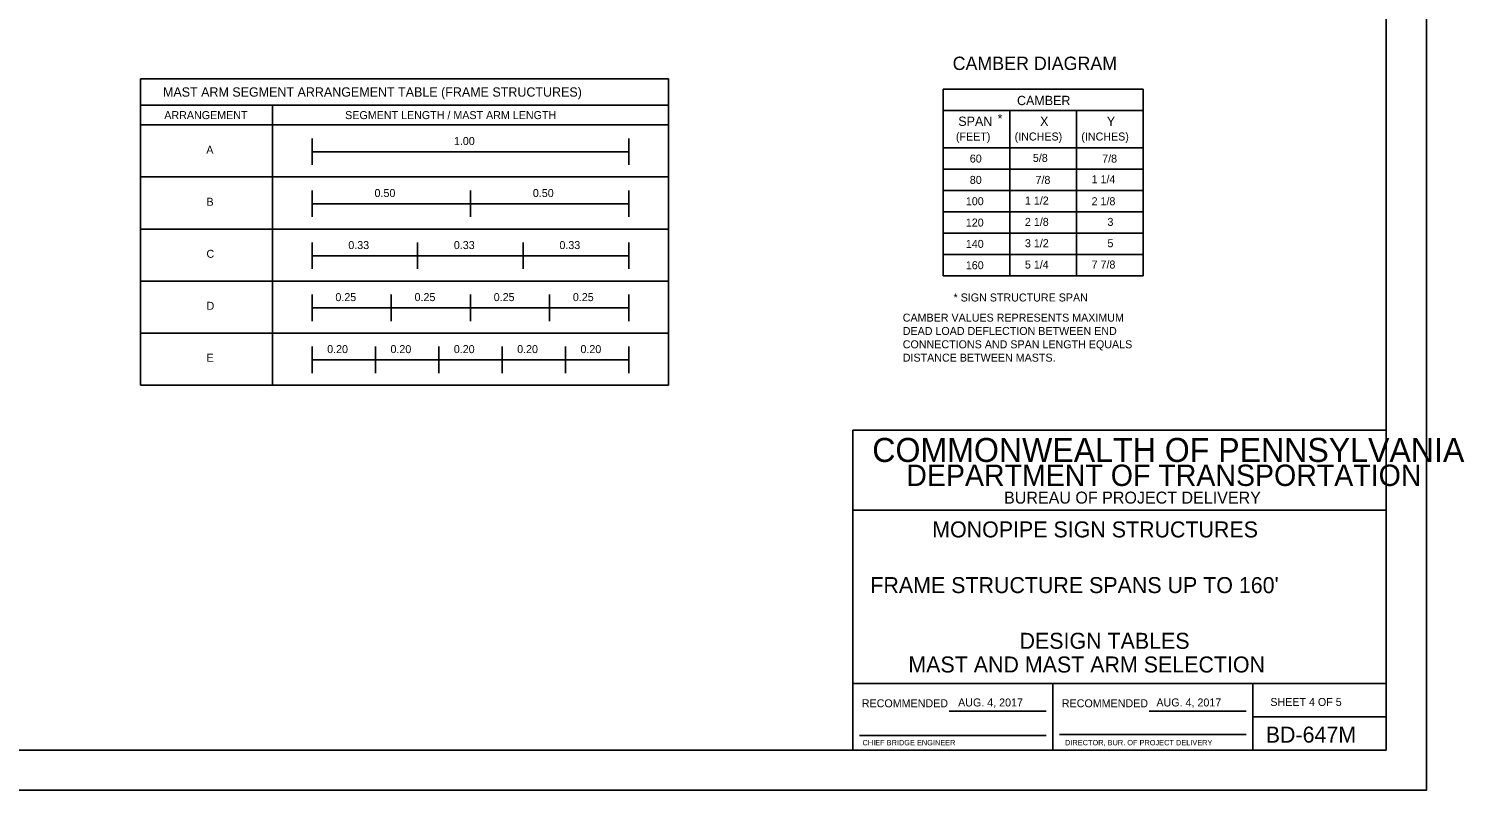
# Model space of a CAD drawing. Extents: x 640117 to 642655, y 297247 to 298435.
# Drawn here: x 641275 to 641814, y 297247 to 297533 of the extents above; entities that cross this region are included whole.
import ezdxf

# ---------------------------------------------------------------- set-up
doc = ezdxf.new("R2010")
doc.units = 0
for name, color, linetype in [('1', 7, 'Continuous'), ('10', 7, 'Continuous'), ('2', 7, 'Continuous'), ('3', 7, 'Continuous'), ('52', 7, 'Continuous'), ('53', 7, 'Continuous'), ('PLT-BNDY', 7, 'Continuous')]:
    doc.layers.add(name, color=color, linetype=linetype)

msp = doc.modelspace()

# ---------------------------------------------------------------- linework, layer by layer
at = {"layer": '1'}
for p, q in [((641659.46, 297262.46), (641659.46, 297287.46)), ((641620.54, 297277.17), (641656.96, 297277.17)), ((641695.54, 297277.17), (641731.96, 297277.17)), ((641586.96, 297267.96), (641656.96, 297267.96)), ((641661.96, 297268.33), (641731.96, 297268.33))]:
    msp.add_line(p, q, dxfattribs=at)
at = {"layer": '2'}
for p, q in [((641784.46, 297826.46), (641784.46, 297262.46)), ((641784.46, 297382.46), (641584.46, 297382.46)), ((641584.46, 297382.46), (641584.46, 297262.46)), ((641784.46, 297262.46), (641784.46, 297382.46)), ((641784.46, 297352.46), (641584.46, 297352.46)), ((641784.46, 297287.46), (641584.46, 297287.46)), ((641734.46, 297287.46), (641734.46, 297262.46)), ((641734.46, 297274.96), (641784.46, 297274.96)), ((641784.46, 297262.46), (640998.46, 297262.46)), ((641584.46, 297262.46), (641784.46, 297262.46))]:
    msp.add_line(p, q, dxfattribs=at)
at = {"layer": '3'}
for p, q in [((641317.35, 297514.26), (641515.24, 297514.26)), ((641317.35, 297514.26), (641317.35, 297399.41)), ((641515.24, 297514.26), (641515.24, 297399.41)), ((641618.23, 297510.34), (641693.23, 297510.34)), ((641618.23, 297510.34), (641618.23, 297440.35)), ((641693.23, 297510.34), (641693.23, 297440.35)), ((641317.35, 297504.36), (641515.24, 297504.36)), ((641366.83, 297504.36), (641366.83, 297399.41)), ((641618.23, 297502.34), (641693.23, 297502.34)), ((641643.23, 297502.34), (641643.23, 297440.35)), ((641668.23, 297502.34), (641668.23, 297440.35)), ((641317.35, 297496.94), (641515.24, 297496.94)), ((641381.67, 297491.85), (641381.67, 297481.95)), ((641500.4, 297491.85), (641500.4, 297481.95)), ((641381.67, 297486.9), (641500.4, 297486.9)), ((641618.23, 297488.34), (641693.23, 297488.34)), ((641618.23, 297480.34), (641693.23, 297480.34)), ((641317.35, 297477.44), (641515.24, 297477.44)), ((641381.67, 297472.34), (641381.67, 297462.45)), ((641441.03, 297472.34), (641441.03, 297462.45)), ((641500.4, 297472.34), (641500.4, 297462.45)), ((641618.23, 297472.35), (641693.23, 297472.35)), ((641381.67, 297467.39), (641441.03, 297467.39)), ((641441.03, 297467.39), (641500.4, 297467.39)), ((641618.23, 297464.35), (641693.23, 297464.35)), ((641317.35, 297457.93), (641515.24, 297457.93)), ((641381.67, 297452.83), (641381.67, 297442.94)), ((641421.24, 297452.83), (641421.24, 297442.94)), ((641460.82, 297452.83), (641460.82, 297442.94)), ((641500.4, 297452.83), (641500.4, 297442.94)), ((641618.23, 297456.35), (641693.23, 297456.35)), ((641381.67, 297447.89), (641421.24, 297447.89)), ((641421.24, 297447.89), (641460.82, 297447.89)), ((641460.82, 297447.89), (641500.4, 297447.89)), ((641618.23, 297448.35), (641693.23, 297448.35)), ((641317.35, 297438.42), (641515.24, 297438.42)), ((641618.23, 297440.35), (641693.23, 297440.35)), ((641381.67, 297433.33), (641381.67, 297423.43)), ((641411.35, 297433.33), (641411.35, 297423.43)), ((641441.03, 297433.33), (641441.03, 297423.43)), ((641470.71, 297433.33), (641470.71, 297423.43)), ((641500.4, 297433.33), (641500.4, 297423.43)), ((641381.67, 297428.38), (641411.35, 297428.38)), ((641411.35, 297428.38), (641441.03, 297428.38)), ((641441.03, 297428.38), (641470.71, 297428.38)), ((641470.71, 297428.38), (641500.4, 297428.38)), ((641317.35, 297418.91), (641515.24, 297418.91)), ((641381.67, 297413.82), (641381.67, 297403.93)), ((641405.41, 297413.82), (641405.41, 297403.93)), ((641429.16, 297413.82), (641429.16, 297403.93)), ((641452.9, 297413.82), (641452.9, 297403.93)), ((641476.65, 297413.82), (641476.65, 297403.93)), ((641500.4, 297413.82), (641500.4, 297403.93)), ((641381.67, 297408.87), (641405.41, 297408.87)), ((641405.41, 297408.87), (641429.16, 297408.87)), ((641429.16, 297408.87), (641452.9, 297408.87)), ((641452.9, 297408.87), (641476.65, 297408.87)), ((641476.65, 297408.87), (641500.4, 297408.87)), ((641317.35, 297399.41), (641515.24, 297399.41))]:
    msp.add_line(p, q, dxfattribs=at)
at = {"layer": 'PLT-BNDY'}
msp.add_lwpolyline([(640958.46, 297841.46), (641799.46, 297841.46), (641799.46, 297247.46), (640958.46, 297247.46)], close=True, dxfattribs=at)

# ---------------------------------------------------------------- texts
at = {"layer": '1'}
for s, height, p in [('RECOMMENDED', 3, (641587.79, 297278.58)), ('RECOMMENDED', 3, (641662.79, 297278.58)), ('CHIEF BRIDGE ENGINEER', 2.0002, (641588.05, 297264.33)), ('DIRECTOR, BUR. OF PROJECT DELIVERY', 2.0002, (641664, 297264.33))]:
    msp.add_text(s, height=height, dxfattribs=at).set_placement(p)
at = {"layer": '10'}
for s, p in [('MONOPIPE SIGN STRUCTURES', (641614.18, 297342.28)), ("FRAME STRUCTURE SPANS UP TO 160'", (641590.98, 297321.4)), ('DESIGN TABLES', (641646.92, 297300.51)), ('MAST AND MAST ARM SELECTION', (641605.23, 297291.63)), ('BD-647M', (641739.25, 297265.33))]:
    msp.add_text(s, height=6, dxfattribs=at).set_placement(p)
at = {"layer": '2'}
for s, height, p in [('COMMONWEALTH OF PENNSYLVANIA', 9, (641591.71, 297370.58)), ('DEPARTMENT OF TRANSPORTATION', 8.0002, (641604.46, 297361.58)), ('BUREAU OF PROJECT DELIVERY', 4.5, (641641.12, 297354.96)), ('SHEET 4 OF 5', 3, (641740.97, 297279.08))]:
    msp.add_text(s, height=height, dxfattribs=at).set_placement(p)
at = {"layer": '52'}
for p in [(641623.89, 297278.89), (641698.25, 297278.89)]:
    msp.add_text('AUG. 4, 2017', height=3, dxfattribs=at).set_placement(p)
at = {"layer": '53'}
for s, height, p in [('CAMBER DIAGRAM', 5, (641621.84, 297517.57)), ('MAST ARM SEGMENT ARRANGEMENT TABLE (FRAME STRUCTURES)', 3.5, (641325.75, 297507.56)), ('CAMBER', 3.5, (641645.98, 297504.38)), ('ARRANGEMENT', 3, (641326.23, 297499.15)), ('SEGMENT LENGTH / MAST ARM LENGTH', 3, (641394.06, 297499.15)), ('*', 3.5, (641638.7, 297497.61)), ('SPAN', 3.5, (641623.96, 297496.59)), ('X', 3.5, (641654.64, 297496.59)), ('Y', 3.5, (641679.64, 297496.59)), ('1.00', 3, (641434.83, 297489.42)), ('(FEET)', 3, (641623.07, 297491.12)), ('(INCHES)', 3, (641645.09, 297491.12)), ('(INCHES)', 3, (641670.09, 297491.12)), ('A', 3, (641341.98, 297486.16)), ('60', 3, (641628.28, 297482.84)), ('5/8 ', 3, (641651.92, 297483.1)), ('7/8', 3, (641677.91, 297482.84)), ('80', 3, (641628.28, 297474.85)), ('7/8', 3, (641652.91, 297474.85)), ('1 1/4', 3, (641673.94, 297475.1)), ('B', 3, (641342.04, 297466.65)), ('0.50', 3, (641405.07, 297469.92)), ('0.50', 3, (641464.44, 297469.92)), ('100', 3, (641626.79, 297466.85)), ('1 1/2', 3, (641648.94, 297467.1)), ('2 1/8', 3, (641673.94, 297466.85)), ('120', 3, (641626.79, 297458.85)), ('2 1/8', 3, (641648.94, 297459.1)), ('3', 3, (641679.89, 297459.1)), ('0.33', 3, (641395.24, 297450.41)), ('0.33', 3, (641434.81, 297450.41)), ('0.33', 3, (641474.39, 297450.41)), ('140', 3, (641626.79, 297450.85)), ('3 1/2', 3, (641648.94, 297451.11)), ('5', 3, (641679.89, 297451.11)), ('C', 3, (641342.05, 297447.14)), ('160', 3, (641626.79, 297442.85)), ('5 1/4', 3, (641648.94, 297443.11)), ('7 7/8', 3, (641673.94, 297443.11)), ('D', 3, (641342.08, 297427.63)), ('0.25', 3, (641390.39, 297430.9)), ('0.25', 3, (641420.08, 297430.9)), ('0.25', 3, (641449.76, 297430.9)), ('0.25', 3, (641479.44, 297430.9)), ('* SIGN STRUCTURE SPAN', 3, (641622.17, 297430.76)), ('CAMBER VALUES REPRESENTS MAXIMUM', 3, (641603.13, 297423.2)), ('DEAD LOAD DEFLECTION BETWEEN END', 3, (641603.13, 297418.2)), ('0.20', 3, (641387.3, 297411.4)), ('0.20', 3, (641411.04, 297411.4)), ('0.20', 3, (641434.79, 297411.4)), ('0.20', 3, (641458.54, 297411.4)), ('0.20', 3, (641482.28, 297411.4)), ('CONNECTIONS AND SPAN LENGTH EQUALS', 3, (641603.13, 297413.2)), ('E', 3, (641342.08, 297408.13)), ('DISTANCE BETWEEN MASTS.', 3, (641603.13, 297408.2))]:
    msp.add_text(s, height=height, dxfattribs=at).set_placement(p)

doc.saveas('drawing.dxf')
